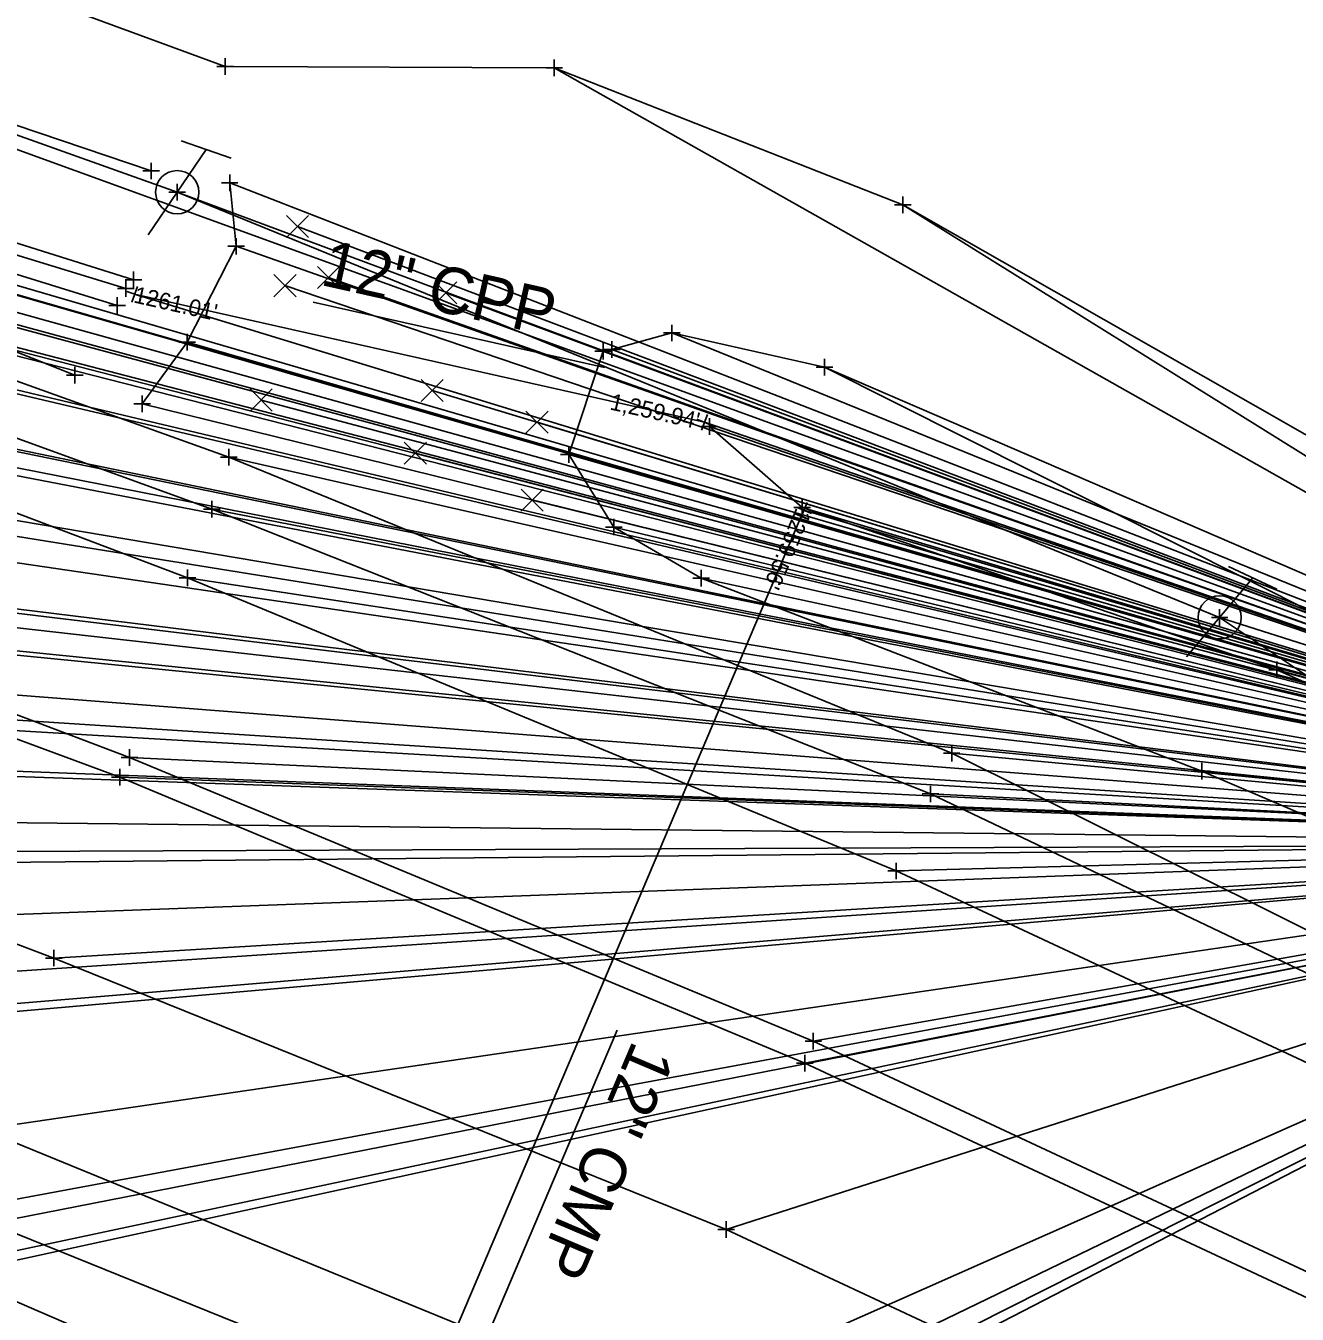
# Model space of a CAD drawing. Extents: x 125846 to 128609, y 511011 to 513388.
# Drawn here: x 126154 to 126230.6, y 513263 to 513340.6 of the extents above; entities that cross this region are included whole.
import ezdxf

# ---------------------------------------------------------------- set-up
doc = ezdxf.new("R2010")
doc.units = 0
for name, color, linetype in [('Default', 7, 'Continuous'), ('DR_X_Ditch', 7, 'Continuous'), ('DR_X_Elev_Flow', 7, 'Continuous'), ('DR_X_Storm_Sewer', 7, 'Continuous'), ('DR_X_Text', 7, 'Continuous'), ('DT_X_Terrain_Boundary', 7, 'Continuous'), ('PM_X_CL_Double_Solid', 7, 'Continuous'), ('PM_X_Edge_Line', 7, 'Continuous'), ('PM_X_Lane_Line', 7, 'Continuous'), ('PV_X_COP', 7, 'Continuous'), ('PV_X_EOP', 7, 'Continuous'), ('PV_X_Shoulder_Aggregate', 7, 'Continuous'), ('RD_X_GR_Lt', 7, 'Continuous'), ('SC_Scratch1', 7, 'Continuous'), ('SV_Observation', 7, 'Continuous'), ('SV_X_Break_Lines', 7, 'Continuous'), ('UT_X_Gas', 7, 'Continuous'), ('UT_X_Overhead_Cable_TV', 7, 'Continuous'), ('UT_X_Overhead_Telecom', 7, 'Continuous'), ('UT_X_Sanitary_Line', 7, 'Continuous'), ('UT_X_Water', 7, 'Continuous')]:
    doc.layers.add(name, color=color, linetype=linetype)

msp = doc.modelspace()

# ---------------------------------------------------------------- linework, layer by layer
at = {"layer": 'Default'}
for points in [[(126194.859, 513316.742), (126160.521, 513324.455)], [(126200.851, 513311.444), (126200.851, 513311.444)]]:
    msp.add_lwpolyline(points, dxfattribs=at)
at = {"layer": 'DR_X_Ditch'}
for points in [[(126160.449, 513325.318), (126127.604, 513335.671), (126093.533, 513347.577), (126052.352, 513361.002), (126025.759, 513369.863)], [(126159.47, 513323.785), (126126.998, 513333.834), (126093.25, 513345.476), (126051.873, 513358.9), (126025.631, 513367.443)], [(126195.167, 513316.49), (126200.745, 513311.612), (126229.35, 513301.828), (126257.004, 513289.515), (126289.161, 513269.766), (126310.452, 513252.79), (126330.741, 513231.106), (126357.384, 513204.313), (126382.668, 513182.292), (126411.183, 513153.266), (126435.19, 513123.215), (126452.39, 513101.071), (126468.552, 513078.137), (126484.851, 513054.484)]]:
    msp.add_lwpolyline(points, dxfattribs=at)
at = {"layer": 'DR_X_Elev_Flow'}
for p, q in [((126160.685, 513324.928), (126160.357, 513323.983)), ((126160.048, 513324.619), (126160.993, 513324.291)), ((126160.521, 513324.455), (126160.521, 513324.455)), ((126195.047, 513317.206), (126194.671, 513316.279)), ((126194.395, 513316.931), (126195.322, 513316.554)), ((126194.859, 513316.742), (126194.859, 513316.742)), ((126200.39, 513311.638), (126201.312, 513311.251)), ((126201.044, 513311.906), (126200.657, 513310.983)), ((126200.851, 513311.444), (126200.851, 513311.444))]:
    msp.add_line(p, q, dxfattribs=at)
at = {"layer": 'DR_X_Storm_Sewer'}
for p, q in [((126160.521, 513324.455), (126194.859, 513316.742)), ((126200.851, 513311.444), (126168.785, 513236.065))]:
    msp.add_line(p, q, dxfattribs=at)
at = {"layer": 'DR_X_Text'}
for p, q in [((126188.831, 513320.044), (126171.284, 513323.985)), ((126181.973, 513262.212), (126189.594, 513280.129))]:
    msp.add_line(p, q, dxfattribs=at)
at = {"layer": 'DT_X_Terrain_Boundary'}
msp.add_lwpolyline([(126654.157, 512850.162), (126631.911, 512886.666), (126606.283, 512922.43), (126575.145, 512962.99), (126554.398, 513001.48), (126537.397, 513030.12), (126511.454, 513071.515), (126472.46, 513118.231), (126457.827, 513153.02), (126432.864, 513170.932), (126397.359, 513201.962), (126378.193, 513217.018), (126342.519, 513242.078), (126323.461, 513259.025), (126297.531, 513278.347), (126261.654, 513302.498), (126237.007, 513312.611), (126206.81, 513329.835), (126185.807, 513338.099), (126165.97, 513338.18), (126131.113, 513350.986), (126098.26, 513361.073)], dxfattribs=at)
at = {"layer": 'PM_X_CL_Double_Solid'}
msp.add_lwpolyline([(126636.017, 512759.401), (126615.052, 512794.202), (126593.251, 512831.822), (126573.13, 512865.785), (126548.621, 512907.965), (126527.484, 512943.531), (126502.23, 512985.512), (126481.231, 513018.849), (126459.488, 513051.362), (126435.341, 513083.61), (126410.097, 513114.165), (126382.091, 513143.772), (126354.344, 513170.576), (126324.593, 513194.517), (126296.415, 513214.573), (126261.191, 513235.428), (126226.405, 513253.988), (126196.16, 513268.127), (126155.649, 513284.478), (126122.948, 513296.874), (126084.02, 513309.984), (126040.97, 513324.805)], dxfattribs=at)
at = {"layer": 'PM_X_Edge_Line'}
for points in [[(126646.482, 512764.297), (126625.047, 512800.492), (126603.518, 512837.499), (126583.42, 512871.084), (126558.648, 512913.238), (126536.506, 512950.368), (126511.991, 512991.15), (126491.968, 513023.231), (126469.188, 513056.956), (126444.768, 513089.911), (126418.586, 513121.925), (126390.317, 513151.799), (126361.214, 513179.136), (126334.356, 513202.694), (126323.484, 513214.345), (126307.58, 513231.462), (126297.55, 513240.362), (126282.403, 513251.31), (126239.764, 513274.153), (126206.406, 513289.72), (126163.701, 513307.371), (126132.055, 513319.352), (126092.674, 513333.111), (126048.479, 513348.099)], [(126641.905, 512726.192), (126625.341, 512754.344), (126605.082, 512788.942), (126583.363, 512826.685), (126563.043, 512860.474), (126538.921, 512902.029), (126518.321, 512936.116), (126492.371, 512979.058), (126471.347, 513012.496), (126449.877, 513044.716), (126425.491, 513077.802), (126401.137, 513107.449), (126374.192, 513136.081), (126346.624, 513162.233), (126316.54, 513186.438), (126289.703, 513205.321), (126254.945, 513226.416), (126221.016, 513243.963), (126192.101, 513257.475), (126151.319, 513274.164), (126119.388, 513285.846), (126084.836, 513297.828), (126036.984, 513314.187)]]:
    msp.add_lwpolyline(points, dxfattribs=at)
at = {"layer": 'PM_X_Lane_Line'}
msp.add_lwpolyline([(126266.572, 513246.35), (126232.12, 513263.571), (126200.904, 513278.147), (126159.634, 513295.376), (126127.349, 513307.308), (126090.732, 513319.939), (126044.365, 513335.461)], dxfattribs=at)
at = {"layer": 'PV_X_COP'}
msp.add_lwpolyline([(126636.017, 512759.401), (126615.052, 512794.202), (126593.251, 512831.822), (126573.13, 512865.785), (126548.621, 512907.965), (126527.484, 512943.531), (126502.23, 512985.512), (126481.231, 513018.849), (126459.488, 513051.362), (126435.341, 513083.61), (126410.097, 513114.165), (126382.091, 513143.772), (126354.344, 513170.576), (126324.593, 513194.517), (126296.415, 513214.573), (126261.191, 513235.428), (126226.405, 513253.988), (126196.16, 513268.127), (126155.649, 513284.478), (126122.948, 513296.874), (126084.02, 513309.984), (126040.97, 513324.805)], dxfattribs=at)
at = {"layer": 'PV_X_EOP'}
for points in [[(126650.635, 512766.087), (126628.045, 512803.924), (126607.089, 512839.247), (126585.955, 512875.064), (126562.15, 512915.456), (126540.109, 512952.487), (126516.436, 512993.225), (126495.399, 513026.664), (126473.144, 513059.705), (126448.57, 513093.109), (126422.469, 513125.427), (126394.043, 513154.56), (126364.862, 513182.317), (126336.405, 513206.05), (126325.917, 513216.487), (126309.901, 513234.823), (126300.61, 513243.728), (126284.181, 513255.062), (126242.92, 513277.962), (126208.476, 513294.357), (126165.175, 513311.518), (126132.696, 513323.32), (126093.947, 513335.924), (126049.366, 513350.889)], [(126637.975, 512724.063), (126621.534, 512752.009), (126602.029, 512784.443), (126578.509, 512824.306), (126558.068, 512859.516), (126534.259, 512899.492), (126514.015, 512933.732), (126488.132, 512977.209), (126467.93, 513009.244), (126445.313, 513042.522), (126421.523, 513074.548), (126397.026, 513104.155), (126370.975, 513132.025), (126342.574, 513158.56), (126313.709, 513182.075), (126286.685, 513201.08), (126252.27, 513222.551), (126219.111, 513239.857), (126189.652, 513253.203), (126149.867, 513269.301), (126117, 513281.261), (126083.105, 513293.411), (126035.314, 513309.488)]]:
    msp.add_lwpolyline(points, dxfattribs=at)
at = {"layer": 'PV_X_Shoulder_Aggregate'}
msp.add_lwpolyline([(126654.698, 512768.66), (126631.692, 512807.538), (126611.89, 512841.644), (126590.711, 512878.21), (126567.344, 512917.946), (126545.014, 512956.03), (126521.833, 512995.466), (126499.82, 513029.911), (126477.051, 513062.237), (126452.128, 513096.451), (126423.22, 513129.468), (126396.106, 513157.038), (126366.787, 513184.791), (126338.939, 513209.02), (126328.274, 513218.539), (126312.088, 513236.867), (126302.886, 513246.154), (126285.647, 513257.485), (126243.687, 513279.934), (126209.75, 513296.807), (126166.204, 513314.648), (126132.94, 513326.563), (126095.739, 513339.378)], dxfattribs=at)
at = {"layer": 'RD_X_GR_Lt'}
msp.add_lwpolyline([(126634.881, 512722.093), (126619.213, 512748.781), (126598.896, 512782.206), (126574.925, 512822.94), (126554.612, 512857.112), (126530.538, 512897.755), (126510.253, 512931.785), (126484.514, 512975.027), (126464.6, 513006.576), (126442.117, 513040.338), (126418.42, 513072.377), (126393.857, 513101.966), (126367.836, 513128.84), (126340.287, 513155.365), (126310.98, 513178.924), (126284.673, 513197.831), (126250.349, 513218.8), (126216.708, 513235.843), (126185.963, 513249.689), (126148.628, 513265.847), (126115.89, 513278.617), (126082.391, 513290.603), (126034.53, 513306.505)], dxfattribs=at)
at = {"layer": 'SV_Observation'}
for p in [(126019.813, 513381.694), (126019.813, 513381.694), (126019.813, 513381.694), (126050.623, 513355.008), (126049.366, 513350.889), (126048.479, 513348.099), (126070.82, 513348.151), (126072.253, 513347.685), (126095.739, 513339.378), (126185.807, 513338.099), (126045.016, 513337.469), (126093.947, 513335.924), (126044.365, 513335.461), (126092.674, 513333.111), (125938.03, 513331.206), (125938.03, 513331.206), (125938.03, 513331.206), (126166.248, 513331.164), (126163.086, 513330.602), (126163.086, 513330.602), (126163.086, 513330.602), (126206.81, 513329.835), (126127.607, 513329.409), (126170.334, 513328.539), (126166.634, 513327.343), (126132.94, 513326.563), (126040.97, 513324.805), (126040.97, 513324.805), (126169.581, 513324.978), (126172.203, 513325.459), (126160.521, 513324.455), (126179.27, 513324.539), (126101.909, 513323.444), (126132.696, 513323.32), (126192.887, 513322.123), (126090.59, 513321.439), (126163.687, 513321.567), (126188.753, 513321.02), (126189.279, 513321.136), (126090.732, 513319.939), (126132.055, 513319.352), (126202.085, 513320.061), (126178.448, 513318.662), (126160.972, 513317.863), (126168.143, 513318.084), (126184.765, 513316.746), (126194.859, 513316.742), (126195.167, 513316.49), (126177.43, 513314.881), (126186.687, 513314.801), (126036.984, 513314.187), (126166.204, 513314.648), (126184.479, 513312.05), (126200.745, 513311.612), (126165.175, 513311.518), (126200.851, 513311.444), (126189.394, 513310.436), (126035.314, 513309.488), (126084.02, 513309.984), (126084.02, 513309.984), (126128.608, 513308.549), (126127.349, 513307.308), (126163.701, 513307.371), (126194.654, 513307.359), (126034.53, 513306.505), (126033.871, 513305.233), (126225.895, 513304.994), (126225.895, 513304.994), (126225.895, 513304.994), (126229.35, 513301.828), (126084.836, 513297.828), (126122.948, 513296.874), (126122.948, 513296.874), (126160.22, 513296.56), (126209.75, 513296.807), (126159.634, 513295.376), (126224.816, 513295.731), (126208.476, 513294.357), (126083.105, 513293.411), (126082.213, 513289.546), (126082.391, 513290.603), (126114.738, 513277.882), (126115.89, 513278.617), (126117, 513281.261), (126119.388, 513285.846), (126131.861, 513264.581), (126131.861, 513264.581), (126131.861, 513264.581), (126148.501, 513265.208), (126148.628, 513265.847), (126149.867, 513269.301), (126151.319, 513274.164), (126155.649, 513284.478), (126155.649, 513284.478), (126185.963, 513249.689), (126185.966, 513248.746), (126189.652, 513253.203), (126192.101, 513257.475), (126196.16, 513268.127), (126196.16, 513268.127), (126200.904, 513278.147), (126201.412, 513279.468), (126206.406, 513289.72)]:
    msp.add_line(p, (126268.599, 513291.356), dxfattribs=at)
at = {"layer": 'SV_X_Break_Lines'}
for points in [[(126165.97, 513338.18), (126131.113, 513350.986), (126098.26, 513361.073), (126057.964, 513376.737), (126032.136, 513387.827)], [(126161.523, 513331.879), (126130.379, 513342.437), (126096.156, 513354.105), (126055.284, 513369.26), (126028.571, 513377.46)], [(126159.986, 513324.809), (126127.522, 513334.737), (126093.233, 513346.612), (126052.1, 513359.978), (126025.535, 513368.618)], [(126156.915, 513319.581), (126126.342, 513331.749), (126092.154, 513342.095), (126051.024, 513355.936), (126025.235, 513365.511)], [(126185.807, 513338.099), (126206.81, 513329.835), (126237.007, 513312.611), (126261.654, 513302.498), (126297.531, 513278.347), (126323.461, 513259.025), (126342.694, 513241.731), (126378.568, 513216.448), (126397.359, 513201.962), (126432.864, 513170.932), (126457.827, 513153.02), (126472.46, 513118.231), (126490.616, 513097.071), (126511.454, 513071.515), (126537.397, 513030.12), (126554.398, 513001.48), (126575.145, 512962.99), (126606.283, 512922.43), (126631.911, 512886.666), (126654.157, 512850.162), (126677.525, 512807.817), (126699.78, 512775.901)], [(126327.877, 513206.006), (126302.562, 513224.622), (126267.083, 513247.702), (126232.5, 513264.958), (126201.412, 513279.468), (126160.22, 513296.56), (126128.608, 513308.549), (126090.59, 513321.439), (126045.016, 513337.469)], [(126160.972, 513317.863), (126163.687, 513321.567), (126166.634, 513327.343), (126166.248, 513331.164)], [(126189.279, 513321.136), (126192.887, 513322.123), (126202.085, 513320.061), (126231.79, 513305.143), (126257.863, 513292.476), (126292.177, 513271.647), (126315.585, 513254.127), (126335.528, 513234.092), (126359.419, 513205.692), (126385.442, 513185.583), (126415.687, 513155.044), (126439.037, 513127.553), (126455.309, 513104.231), (126471.515, 513078.977), (126486.388, 513055.874), (126513.084, 513014.872), (126523.408, 512998.478), (126531.629, 512982.695), (126553.062, 512948.526), (126576.564, 512910.23), (126598.961, 512870.118), (126622.128, 512830.629), (126647.104, 512787.847), (126663.978, 512759.85)], [(126188.753, 513321.02), (126186.687, 513314.801), (126189.394, 513310.436), (126194.654, 513307.359), (126224.816, 513295.731), (126253.817, 513283.309), (126284.164, 513265.563), (126305.887, 513248.889), (126325.134, 513229.25), (126354.04, 513199.869), (126380.32, 513179.574), (126408.047, 513150.59), (126432.721, 513121.523), (126450.633, 513100.036), (126466.911, 513077.345)]]:
    msp.add_lwpolyline(points, dxfattribs=at)
at = {"layer": 'UT_X_Gas'}
for p, q in [((126166.341, 513332.646), (126163.319, 513333.697)), ((126164.83, 513333.171), (126161.342, 513328.032)), ((126229.339, 513306.702), (126226.437, 513308.05)), ((126227.888, 513307.376), (126223.903, 513302.612))]:
    msp.add_line(p, q, dxfattribs=at)
for centre in [(126163.086, 513330.602), (126225.896, 513304.994)]:
    msp.add_circle(centre, 1.3, dxfattribs=at)
at = {"layer": 'UT_X_Overhead_Cable_TV'}
msp.add_lwpolyline([(127151.135, 511501.172), (127120.309, 511642.52), (127100.367, 511762.141), (127071.139, 511920.25), (127038.245, 512070.716), (126995.9, 512201.988), (126951.927, 512290.638), (126888.078, 512393.934), (126821.569, 512508.62), (126750.649, 512627.876), (126677.44, 512750.383), (126606.516, 512869.514), (126525.52, 513001.821), (126518.89, 513012.818), (126445.697, 513128.427), (126355.465, 513218.249), (126225.896, 513304.994), (126163.086, 513330.602), (126019.813, 513381.694)], dxfattribs=at)
at = {"layer": 'UT_X_Overhead_Telecom'}
msp.add_lwpolyline([(127151.135, 511501.172), (127120.309, 511642.52), (127100.367, 511762.141), (127071.139, 511920.25), (127038.245, 512070.716), (126995.9, 512201.988), (126951.927, 512290.638), (126888.078, 512393.934), (126821.569, 512508.62), (126750.649, 512627.876), (126677.44, 512750.383), (126606.516, 512869.514), (126525.52, 513001.821), (126518.89, 513012.818), (126445.697, 513128.427), (126354.464, 513218.752), (126225.896, 513304.994), (126163.086, 513330.602), (126019.813, 513381.694)], dxfattribs=at)
at = {"layer": 'UT_X_Sanitary_Line'}
for p, q in [((126165.47, 513338.18), (126166.47, 513338.18)), ((126165.97, 513338.68), (126165.97, 513337.68)), ((126165.97, 513338.18), (126165.97, 513338.18)), ((126185.307, 513338.099), (126186.307, 513338.099)), ((126185.807, 513338.599), (126185.807, 513337.599)), ((126185.807, 513338.099), (126185.807, 513338.099)), ((126161.023, 513331.879), (126162.023, 513331.879)), ((126161.523, 513332.379), (126161.523, 513331.379)), ((126161.523, 513331.879), (126161.523, 513331.879)), ((126163.086, 513331.102), (126163.086, 513330.102)), ((126163.086, 513331.102), (126163.086, 513330.102)), ((126165.748, 513331.164), (126166.748, 513331.164)), ((126166.248, 513331.664), (126166.248, 513330.664)), ((126166.248, 513331.164), (126166.248, 513331.164)), ((126162.586, 513330.602), (126163.586, 513330.602)), ((126162.586, 513330.602), (126163.586, 513330.602)), ((126163.086, 513330.602), (126163.086, 513330.602)), ((126163.086, 513330.602), (126163.086, 513330.602)), ((126206.81, 513330.335), (126206.81, 513329.335)), ((126206.31, 513329.835), (126207.31, 513329.835)), ((126206.81, 513329.835), (126206.81, 513329.835)), ((126166.134, 513327.343), (126167.134, 513327.343)), ((126166.634, 513327.843), (126166.634, 513326.843)), ((126166.634, 513327.343), (126166.634, 513327.343)), ((126160.449, 513325.818), (126160.449, 513324.818)), ((126159.486, 513324.809), (126160.486, 513324.809)), ((126159.949, 513325.318), (126160.949, 513325.318)), ((126159.986, 513325.309), (126159.986, 513324.309)), ((126159.986, 513324.809), (126159.986, 513324.809)), ((126160.449, 513325.318), (126160.449, 513325.318)), ((126159.47, 513324.285), (126159.47, 513323.285)), ((126158.97, 513323.785), (126159.97, 513323.785)), ((126159.47, 513323.785), (126159.47, 513323.785)), ((126192.887, 513322.623), (126192.887, 513321.623)), ((126163.687, 513322.067), (126163.687, 513321.067)), ((126192.387, 513322.123), (126193.387, 513322.123)), ((126192.887, 513322.123), (126192.887, 513322.123)), ((126163.187, 513321.567), (126164.187, 513321.567)), ((126163.687, 513321.567), (126163.687, 513321.567)), ((126188.253, 513321.02), (126189.253, 513321.02)), ((126188.753, 513321.52), (126188.753, 513320.52)), ((126188.753, 513321.02), (126188.753, 513321.02)), ((126188.779, 513321.136), (126189.779, 513321.136)), ((126189.279, 513321.636), (126189.279, 513320.636)), ((126189.279, 513321.136), (126189.279, 513321.136)), ((126202.085, 513320.561), (126202.085, 513319.561)), ((126156.415, 513319.581), (126157.415, 513319.581)), ((126156.915, 513320.081), (126156.915, 513319.081)), ((126156.915, 513319.581), (126156.915, 513319.581)), ((126201.585, 513320.061), (126202.585, 513320.061)), ((126202.085, 513320.061), (126202.085, 513320.061)), ((126160.472, 513317.863), (126161.472, 513317.863)), ((126160.972, 513318.363), (126160.972, 513317.363)), ((126160.972, 513317.863), (126160.972, 513317.863)), ((126194.667, 513316.49), (126195.667, 513316.49)), ((126195.167, 513316.99), (126195.167, 513315.99)), ((126195.167, 513316.49), (126195.167, 513316.49)), ((126166.204, 513315.148), (126166.204, 513314.148)), ((126186.187, 513314.801), (126187.187, 513314.801)), ((126186.687, 513315.301), (126186.687, 513314.301)), ((126186.687, 513314.801), (126186.687, 513314.801)), ((126165.704, 513314.648), (126166.704, 513314.648)), ((126166.204, 513314.648), (126166.204, 513314.648)), ((126165.175, 513312.018), (126165.175, 513311.018)), ((126200.245, 513311.612), (126201.245, 513311.612)), ((126200.745, 513312.112), (126200.745, 513311.112)), ((126200.745, 513311.612), (126200.745, 513311.612)), ((126164.675, 513311.518), (126165.675, 513311.518)), ((126165.175, 513311.518), (126165.175, 513311.518)), ((126189.394, 513310.936), (126189.394, 513309.936)), ((126188.894, 513310.436), (126189.894, 513310.436)), ((126189.394, 513310.436), (126189.394, 513310.436)), ((126163.701, 513307.871), (126163.701, 513306.871)), ((126194.654, 513307.859), (126194.654, 513306.859)), ((126163.201, 513307.371), (126164.201, 513307.371)), ((126163.701, 513307.371), (126163.701, 513307.371)), ((126194.154, 513307.359), (126195.154, 513307.359)), ((126194.654, 513307.359), (126194.654, 513307.359)), ((126225.896, 513305.494), (126225.896, 513304.494)), ((126225.896, 513305.494), (126225.896, 513304.494)), ((126225.396, 513304.994), (126226.396, 513304.994)), ((126225.396, 513304.994), (126226.396, 513304.994)), ((126225.896, 513304.994), (126225.896, 513304.994)), ((126225.896, 513304.994), (126225.896, 513304.994)), ((126229.35, 513302.328), (126229.35, 513301.328)), ((126228.85, 513301.828), (126229.85, 513301.828)), ((126229.35, 513301.828), (126229.35, 513301.828)), ((126160.22, 513297.06), (126160.22, 513296.06)), ((126209.75, 513297.307), (126209.75, 513296.307)), ((126159.72, 513296.56), (126160.72, 513296.56)), ((126160.22, 513296.56), (126160.22, 513296.56)), ((126209.25, 513296.807), (126210.25, 513296.807)), ((126209.75, 513296.807), (126209.75, 513296.807)), ((126224.816, 513296.231), (126224.816, 513295.231)), ((126159.134, 513295.376), (126160.134, 513295.376)), ((126159.634, 513295.876), (126159.634, 513294.876)), ((126159.634, 513295.376), (126159.634, 513295.376)), ((126224.316, 513295.731), (126225.316, 513295.731)), ((126224.816, 513295.731), (126224.816, 513295.731)), ((126208.476, 513294.857), (126208.476, 513293.857)), ((126207.976, 513294.357), (126208.976, 513294.357)), ((126208.476, 513294.357), (126208.476, 513294.357)), ((126206.406, 513290.22), (126206.406, 513289.22)), ((126205.906, 513289.72), (126206.906, 513289.72)), ((126206.406, 513289.72), (126206.406, 513289.72)), ((126155.149, 513284.478), (126156.149, 513284.478)), ((126155.149, 513284.478), (126156.149, 513284.478)), ((126155.649, 513284.978), (126155.649, 513283.978)), ((126155.649, 513284.978), (126155.649, 513283.978)), ((126155.649, 513284.478), (126155.649, 513284.478)), ((126155.649, 513284.478), (126155.649, 513284.478)), ((126201.412, 513279.968), (126201.412, 513278.968)), ((126200.912, 513279.468), (126201.912, 513279.468)), ((126201.412, 513279.468), (126201.412, 513279.468)), ((126200.904, 513278.647), (126200.904, 513277.647)), ((126200.404, 513278.147), (126201.404, 513278.147)), ((126200.904, 513278.147), (126200.904, 513278.147)), ((126195.66, 513268.127), (126196.66, 513268.127)), ((126195.66, 513268.127), (126196.66, 513268.127)), ((126196.16, 513268.627), (126196.16, 513267.627)), ((126196.16, 513268.627), (126196.16, 513267.627)), ((126196.16, 513268.127), (126196.16, 513268.127)), ((126196.16, 513268.127), (126196.16, 513268.127))]:
    msp.add_line(p, q, dxfattribs=at)
at = {"layer": 'UT_X_Water'}
for p, q in [((126169.667, 513327.871), (126171, 513329.206)), ((126169.667, 513329.206), (126171, 513327.871)), ((126168.914, 513324.31), (126170.248, 513325.645)), ((126168.914, 513325.645), (126170.248, 513324.31)), ((126171.537, 513324.792), (126172.87, 513326.127)), ((126171.537, 513326.127), (126172.87, 513324.792)), ((126178.603, 513323.872), (126179.937, 513325.207)), ((126178.603, 513325.207), (126179.937, 513323.872)), ((126167.477, 513317.417), (126168.81, 513318.752)), ((126167.477, 513318.752), (126168.81, 513317.417)), ((126177.781, 513317.995), (126179.115, 513319.33)), ((126177.781, 513319.33), (126179.115, 513317.995)), ((126184.099, 513316.079), (126185.432, 513317.414)), ((126184.099, 513317.414), (126185.432, 513316.079)), ((126176.763, 513314.213), (126178.097, 513315.548)), ((126176.763, 513315.548), (126178.097, 513314.213)), ((126183.812, 513311.383), (126185.145, 513312.718)), ((126183.812, 513312.718), (126185.145, 513311.383))]:
    msp.add_line(p, q, dxfattribs=at)

# ---------------------------------------------------------------- texts
at = {"layer": 'DR_X_Text'}
for s, rotation, p in [('12" CPP', 347.34059, (126171.637, 513325.035)), ('12" CMP', 246.95586, (126190.563, 513279.592))]:
    msp.add_text(s, height=2.8, rotation=rotation, dxfattribs=at).set_placement(p)
at = {"layer": 'SC_Scratch1'}
for s, rotation, p in [("1261.01'", 347.34059, (126160.411, 513323.967)), ("1,259.94'", 347.34059, (126189.108, 513317.522)), ("1259.56'", 246.95586, (126200.391, 513311.64))]:
    msp.add_text(s, height=1, rotation=rotation, dxfattribs=at).set_placement(p)

doc.saveas('drawing.dxf')
